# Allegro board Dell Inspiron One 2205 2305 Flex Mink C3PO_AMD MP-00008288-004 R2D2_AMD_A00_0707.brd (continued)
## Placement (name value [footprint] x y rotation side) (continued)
R666  75R  [R0402]  16.01 61.98 180 bottom
R667  0R  [R0402]  81.67 71.63 270 bottom
R668  0R  [R0402]  79.89 55.75 90 bottom
R669  2K2  [R0402]  109.1 58.67 0 bottom
R670  11K8  [R0402]  89.09 68.45 270 bottom
R671  931R  [R0402]  108.34 64.77 180 bottom
R672  2K2  [R0402]  109.1 57.4 0 bottom
R673  2K2  [R0402]  109.1 56.13 0 bottom
R674  20K  [R0402]  24.27 57.53 270 bottom
R675  2K2  [R0402]  109.1 54.86 0 bottom
R676  10K  [R0402]  109.1 59.94 180 bottom
R677  10K  [R0402]  81.29 49.4 90 bottom
R678  10K  [R0402]  79 49.4 90 bottom
R679  0R  [R0402]  73.9 57.38 0 bottom
R680  1K  [R0402]  17.28 50.42 0 bottom
R681  0R  [R0402]  73.9 56.24 0 bottom
R682  0R  [R0603]  106.18 52.7 180 bottom
R683  10K  [R0402]  97.67 58.67 270 bottom
R684  100K  [R0402]  178.7 45.34 90 bottom
R685  200K  [R0402]  175.91 48.01 180 bottom
R686  0R  [R0402]  13.09 54.48 180 bottom
R687  0R  [R0603]  93.36 50.67 180 bottom
R688  0R  [R0402]  97.67 53.85 0 bottom
R689  8K2  [R0402]  72.65 52.96 0 bottom
R690  10K  [R0402]  81.04 55.75 270 bottom
R691  4K7  [R0402]  17.28 51.56 180 bottom
R692  1K  [R0402]  164.98 54.74 270 bottom
R693  1K  [R0402]  46.11 41.15 90 bottom
R694  0R  [R0402]  88.91 51.31 0 bottom
R695  1K  [R0402]  18.04 44.2 0 bottom
R696  0R  [R0603]  95.64 52.7 270 bottom
R697  2K2  [R0402]  82.69 52.32 270 bottom
R698  2K2  [R0402]  80.15 52.32 270 bottom
R699  2K2  [R0402]  77.86 52.32 270 bottom
R700  0R  [R0402]  72.27 48.77 0 bottom
R701  10K  [R0402]  27.95 43.81 270 bottom
R702  20K  [R0402]  26.68 43.81 270 bottom
R703  10K  [R0402]  91.32 50.93 270 bottom
R704  0R  [R0402]  190.76 42.67 270 bottom
R705  0R  [R0402]  189.62 42.67 270 bottom
R706  0R  [R0402]  72.3 47.57 0 bottom
R707  0R  [R0402]  124.79 36.96 90 bottom
R708  0R  [R0402]  123.71 36.96 90 bottom
R709  0R  [R0402]  120.66 36.96 90 bottom
R710  15K  [R0402]  119.64 36.96 90 bottom
R711  1K  [R0402]  118.63 36.96 90 bottom
R712  1K  [R0402]  48.21 39.37 180 bottom
R713  4K7  [R0402]  18.04 45.34 180 bottom
R714  0R  [R0603]  87.39 48.13 270 bottom
R715  0R  [R0402]  45.86 35.37 0 bottom
R716  100K  [R0402]  184.29 42.8 180 bottom
R717  0R  [R0402]  43.32 36.45 0 bottom
R718  0R  [R0402]  43.32 37.66 0 bottom
R719  10K  [R0402]  122.69 36.96 270 bottom
R720  10K  [R0402]  121.68 36.96 270 bottom
R721  1K  [R0402]  129.17 34.54 180 bottom
R722  0R  [R0402]  43 33.27 180 bottom
R723  270R  [R0402]  132.85 34.04 180 bottom
R724  10K  [R0402]  120.41 40.89 180 bottom
R725  100K  [R0402]  187.08 39.62 180 bottom
R726  0R  [R0402]  48.91 32.64 0 bottom
R727  0R  [R0402]  45.73 31.37 0 bottom
R728  0R  [R0402]  43.44 31.37 0 bottom
R729  8K2  [R0402]  112.43 27.56 90 bottom
R730  10K  [R0402]  120.91 39.24 270 bottom
R731  1K  [R0402]  115.83 25.15 90 bottom
R732  0R  [R0805]  84.21 133.22 0 top
R733  0R  [R0805]  128.92 37.59 270 bottom
R734  10K  [R0402]  46.11 29.72 270 bottom
R735  0R  [R0402]  114.18 27.05 0 bottom
R736  1K  [R0402]  81.42 206.25 180 top
R737  10K  [R0402]  114.18 26.04 0 bottom
R738  0R  [R0402]  45.1 29.72 90 bottom
R739  1K  [R0402]  114.18 25.02 0 bottom
R740  0R  [R0603]  27.25 25.65 270 bottom
R741  10K  [R0402]  114.18 24 0 bottom
R742  15K  [R0402]  12.2 25.91 270 bottom
R743  100K  [R0603]  25.73 25.65 90 bottom
R744  10K  [R0402]  13.35 28.32 270 top
R745  10K  [R0402]  27.32 22.48 90 bottom
R746  0R  [R0402]  111.36 27.56 270 bottom
R747  2K49  [R0402]  128.47 25.65 270 bottom
R748  0R  [R0402]  44.46 17.53 270 bottom
R749  0R  [R0402]  43.44 17.53 270 bottom
R750  75R  [R0402]  104.23 15.21 0 bottom
R751  100K  [R0402]  26.93 16.7 270 bottom
R752  4K7  [R0402]  12.58 23.05 90 bottom
R753  0R  [R0402]  14.43 24.64 90 top
R754  47K  [R0402]  140.98 15.88 180 bottom
R755  47K  [R0402]  138.82 15.88 180 bottom
R756  0R  [R0603]  33.41 10.72 0 bottom
R757  7K68  [R0603]  24.08 23.11 90 bottom
R758  75R  [R0402]  104.79 12.89 90 bottom
R759  100R  [R0402]  15.38 7.87 0 bottom
R760  0R  [R0603]  30.24 12.57 90 bottom
R761  200K  [R0603]  155.14 20.7 270 bottom
R762  4K7  [R0402]  13.79 7.37 270 bottom
R763  10K  [R0402]  12.77 7.37 270 bottom
R764  0R  [R0402]  11.76 7.37 270 bottom
R765  0R  [R0402]  9.73 7.37 270 bottom
R766  0R  [R0402]  8.71 7.37 270 bottom
R767  2K2  [R0603]  7.44 7.11 90 bottom
R768  22R  [R0402]  6.17 7.18 270 bottom
R769  0R  [R0402]  10.74 7.37 90 bottom
R770  330R  [R0603]  7.95 3.87 90 bottom
R771  1K  [R0402]  27.7 207.26 90 top
R772  20K  [R0402]  99.58 121.16 0 bottom
R773  0R  [R0603]  33.41 8.89 0 bottom
R774  20K  [R0402]  21.66 26.42 90 top
R775  1K  [R0402]  74.31 202.44 270 top
R776  1K  [R0402]  82.81 201.17 90 top
R980  10K  [R0402]  8.46 22.54 180 bottom
R987  0R  [R0402]  10.81 22.54 180 bottom
R989  8K2  [R0402]  21.6 35.69 270 top
R1017  3K3  [R0402]  13.35 26.04 270 top
R2122  4K7  [R0402]  45.86 33.27 180 bottom
R2123  4K7  [R0402]  45.86 34.35 180 bottom
R2124  4K7  [R0402]  40.78 35.69 0 top
R2125  4K7  [R0402]  40.78 36.83 0 top
R2126  0R  [R1206]  77.67 172.91 270 top
R2127  0R  [R1206]  72.4 173.23 270 top
R2128  0R  [R1206]  85.67 133.73 180 bottom
R2129  0R  [R1206]  52.33 161.61 90 bottom
R2130  0R  [R1206]  41.35 143.7 270 bottom
S1  TACT  [DCON_SW_4_DIPTRONICS]  8.05 167.62 90 bottom
S2  TACT  [DCON_SW_4_DIPTRONICS]  8.05 153.62 90 bottom
S3  PUBTON  [DCON_PUBTON_8_HIGHLY-A]  10.79 12.92 270 bottom
SW1  TSXH-2GL  [SCON_SW_4_HUA-JIE]  111.14 34.92 90 top
TP1  STP  [TP30]  20.87 227.84 0 top
TP2  STP  [TP30]  22.84 227.84 0 top
TP3  STP  [TP30]  24.74 227.84 0 top
TP4  STP  [TP30]  26.65 227.84 0 top
TP5  STP  [TP30]  28.55 227.84 0 top
TP6  STP  [TP30]  20.87 225.81 0 top
TP7  STP  [TP30]  22.84 225.81 0 top
TP8  STP  [TP30]  24.74 225.81 0 top
TP9  STP  [TP30]  26.65 225.81 0 top
TP10  STP  [TP30]  28.55 225.81 0 top
TP11  STP  [TP30]  28.93 210.31 0 top
TP12  STP  [TP30]  30.84 210.31 0 top
TP13  STP  [TP30]  32.74 210.31 0 top
TP14  STP  [TP30]  34.65 210.31 0 top
TP15  STP  [TP30]  36.55 210.31 0 top
TP16  STP  [TP30]  17.03 208.53 0 top
TP17  STP  [TP30]  18.93 208.53 0 top
TP18  STP  [TP30]  20.84 208.53 0 top
TP19  STP  [TP30]  22.74 208.53 0 top
TP20  STP  [TP30]  24.65 208.53 0 top
TP21  STP  [TP30]  28.93 208.34 0 top
TP22  STP  [TP30]  30.84 208.34 0 top
TP23  STP  [TP30]  32.74 208.34 0 top
TP24  STP  [TP30]  34.65 208.34 0 top
TP25  STP  [TP30]  36.55 208.34 0 top
TP26  STP  [TP30]  46.79 208.03 0 top
TP27  STP  [TP30]  17.03 206.63 0 top
TP28  STP  [TP30]  18.93 206.63 0 top
TP29  STP  [TP30]  20.84 206.63 0 top
TP30  STP  [TP30]  22.74 206.63 0 top
TP31  STP  [TP30]  24.65 206.63 0 top
TP32  STP  [TP30]  46.87 205.99 0 top
TP33  STP  [TP30]  93.36 162.69 270 top
TP34  STP  [TP30]  89.29 161.54 270 top
TP35  STP  [TP30]  93.36 161.42 270 top
TP36  STP  [TP30]  91.32 164.34 0 top
TP37  STP  [TP30]  89.29 160.27 270 top
TP38  STP  [TP30]  91.2 159.89 270 top
TP39  STP  [TP30]  56.78 163.32 0 top
TP40  STP  [TP30]  91.32 163.07 0 top
TP41  STP  [TP30]  91.2 158.62 270 top
TP42  STP  [TP30]  93.36 158.37 270 top
TP43  STP  [TP30]  89.29 157.23 270 top
TP44  STP  [TP30]  44.84 161.04 0 top
TP45  STP  [TP30]  93.36 157.1 270 top
TP46  STP  [TP30]  89.29 155.96 270 top
TP47  STP  [TP30]  44.84 159.77 0 top
TP48  STP  [TP30]  91.2 155.57 270 top
TP49  STP  [TP30]  91.2 154.31 270 top
TP50  STP  [TP30]  93.23 154.05 270 top
TP51  STP  [TP30]  89.29 152.91 270 top
TP52  STP  [TP30]  89.29 151.64 270 top
TP53  STP  [TP30]  91.32 151.26 270 top
TP54  STP  [TP30]  91.32 149.99 270 top
TP55  STP  [TP30]  93.23 149.73 270 top
TP56  STP  [TP30]  93.23 152.78 0 top
TP57  STP  [TP30]  93.23 148.46 270 top
TP58  STP  [TP30]  160.03 146.94 180 top
TP59  STP  [TP30]  89.16 147.32 270 top
TP60  STP  [TP30]  155.78 149.96 0 top
TP61  STP  [TP30]  91.2 147.07 270 top
TP62  STP  [TP30]  155.79 148.38 0 top
TP63  STP  [TP30]  93.23 145.41 270 top
TP64  STP  [TP30]  89.16 148.59 0 top
TP65  STP  [TP30]  84.21 144.53 270 top
TP66  STP  [TP30]  158.64 146.89 0 top
TP67  STP  [TP30]  93.23 144.15 270 top
TP68  STP  [TP30]  84.21 143.26 270 top
TP69  STP  [TP30]  82.18 143 270 top
TP70  STP  [TP30]  91.2 145.8 0 top
TP71  STP  [TP30]  82.18 141.73 270 top
TP72  STP  [TP30]  84.21 141.35 270 top
TP73  STP  [TP30]  155.8 142.93 0 top
TP74  STP  [TP30]  84.21 140.08 270 top
TP75  STP  [TP30]  82.5 139.83 270 top
TP76  STP  [TP30]  82.5 138.56 270 top
TP77  STP  [TP30]  84.72 138.18 270 top
TP78  STP  [TP30]  84.72 136.91 270 top
TP79  STP  [TP30]  155.83 138.45 0 top
TP80  STP  [TP30]  155.85 135.4 0 top
TP81  STP  [TP30]  82.56 136.4 0 top
TP82  STP  [TP30]  82.56 135.13 0 top
TP83  STP  [TP30]  108.02 120.97 0 top
TP84  STP  [TP30]  129.4 120.45 0 top
TP85  STP  [TP30]  111.64 120.02 0 top
TP86  STP  [TP30]  130.47 119.28 0 top
TP87  STP  [TP30]  96.66 118.75 0 top
TP88  STP  [TP30]  111.64 118.11 0 top
TP89  STP  [TP30]  131.66 118.16 0 top
TP90  STP  [TP30]  97.86 117.2 0 top
TP91  STP  [TP30]  104.66 117.09 0 top
TP92  STP  [TP30]  95.9 116.71 0 top
TP93  STP  [TP30]  132.62 117.04 0 top
TP94  STP  [TP30]  109.1 115.82 0 top
TP95  STP  [TP30]  113.04 72.64 0 top
TP96  STP  [TP30]  77.61 55.24 0 top
TP97  STP  [TP30]  74.05 51.31 0 top
TP98  STP  [TP30]  85.1 49.59 0 top
TP99  STP  [TP30]  112.25 50.62 0 top
TP100  STP  [TP30]  86.75 49.02 0 top
TP101  STP  [TP30]  108.09 50.04 0 top
TP102  STP  [TP30]  91.58 42.67 0 top
TP103  STP  [TP30]  108.85 51.94 180 bottom
TP104  STP  [TP30]  87.01 221.23 180 bottom
TP105  STP  [TP30]  87.01 219.33 180 bottom
TP106  STP  [TP30]  86.94 217.42 180 bottom
TP107  STP  [TP30]  87.01 215.46 180 bottom
TP108  STP  [TP30]  114.44 174.62 180 bottom
TP109  STP  [TP30]  124.92 172.85 180 bottom
TP110  STP  [TP30]  114.06 172.47 180 bottom
TP111  STP  [TP30]  125.99 171.32 180 bottom
TP112  STP  [TP30]  107.58 171.83 180 bottom
TP113  STP  [TP30]  111.52 170.31 180 bottom
TP114  STP  [TP30]  127.01 170.05 180 bottom
TP115  STP  [TP30]  104.28 170.43 180 bottom
TP116  STP  [TP30]  126.25 168.59 180 bottom
TP117  STP  [TP30]  108.21 167.39 180 bottom
TP118  STP  [TP30]  114.56 167.26 180 bottom
TP119  STP  [TP30]  111.99 167.19 180 bottom
TP120  STP  [TP30]  103.01 168.28 180 bottom
TP121  STP  [TP30]  105.8 167.13 180 bottom
TP122  STP  [TP30]  100.85 166.37 180 bottom
TP123  STP  [TP30]  113.29 164.85 180 bottom
TP124  STP  [TP30]  109.48 164.85 180 bottom
TP125  STP  [TP30]  116.72 164.47 180 bottom
TP126  STP  [TP30]  102.88 165.61 180 bottom
TP127  STP  [TP30]  96.15 164.08 180 bottom
TP128  STP  [TP30]  109.48 163.58 180 bottom
TP129  STP  [TP30]  127.52 163.51 180 bottom
TP130  STP  [TP30]  126.19 163.51 180 bottom
TP131  STP  [TP30]  124.85 163.51 180 bottom
TP132  STP  [TP30]  123.45 163.51 180 bottom
TP133  STP  [TP30]  96.15 162.81 180 bottom
TP134  STP  [TP30]  98.05 162.43 180 bottom
TP135  STP  [TP30]  93.86 161.29 180 bottom
TP136  STP  [TP30]  98.05 161.16 180 bottom
TP137  STP  [TP30]  96.02 159.64 180 bottom
TP138  STP  [TP30]  93.86 160.02 180 bottom
TP139  STP  [TP30]  96.02 158.37 180 bottom
TP140  STP  [TP30]  98.05 158.12 180 bottom
TP141  STP  [TP30]  98.05 156.84 180 bottom
TP142  STP  [TP30]  93.99 156.84 180 bottom
TP143  STP  [TP30]  93.99 155.57 180 bottom
TP144  STP  [TP20]  65.42 155.3 180 bottom
TP145  STP  [TP30]  96.02 155.32 180 bottom
TP146  STP  [TP30]  96.02 154.05 180 bottom
TP147  STP  [TP20]  65.44 153.95 180 bottom
TP148  STP  [TP30]  98.05 153.67 180 bottom
TP149  STP  [TP20]  65.39 152.55 180 bottom
TP150  STP  [TP30]  98.05 152.4 180 bottom
TP151  STP  [TP30]  59.57 153.67 180 bottom
TP152  STP  [TP30]  93.99 152.53 180 bottom
TP153  STP  [TP30]  96.02 150.88 180 bottom
TP154  STP  [TP30]  136.35 150.81 180 bottom
TP155  STP  [TP30]  134.31 150.75 180 bottom
TP156  STP  [TP30]  93.99 151.26 180 bottom
TP157  STP  [TP30]  96.02 149.61 180 bottom
TP158  STP  [TP30]  98.05 149.22 180 bottom
TP159  STP  [TP30]  133.81 148.27 180 bottom
TP160  STP  [TP30]  132.47 148.27 180 bottom
TP161  STP  [TP30]  98.05 147.96 180 bottom
TP162  STP  [TP30]  93.99 147.96 180 bottom
TP163  STP  [TP30]  96.15 146.3 180 bottom
TP164  STP  [TP30]  133.68 145.73 180 bottom
TP165  STP  [TP30]  93.99 146.69 180 bottom
TP166  STP  [TP30]  96.15 145.03 180 bottom
TP167  STP  [TP30]  98.05 144.78 180 bottom
TP168  STP  [TP30]  98.05 143.51 180 bottom
TP169  STP  [TP30]  134.82 143.19 180 bottom
TP170  STP  [TP30]  93.99 143.64 180 bottom
TP171  STP  [TP30]  96.15 142.11 180 bottom
TP172  STP  [TP30]  93.99 142.37 180 bottom
TP173  STP  [TP30]  134.38 140.91 180 bottom
TP174  STP  [TP30]  96.15 140.84 180 bottom
TP175  STP  [TP30]  136.28 140.65 180 bottom
TP176  STP  [TP30]  138.72 140.53 180 bottom
TP177  STP  [TP30]  98.05 140.46 180 bottom
TP178  STP  [TP30]  111.01 139.7 180 bottom
TP179  STP  [TP30]  124.79 139.45 180 bottom
TP180  STP  [TP30]  127.33 139.38 180 bottom
TP181  STP  [TP30]  98.05 139.19 180 bottom
TP182  STP  [TP30]  126.06 138.11 180 bottom
TP183  STP  [TP30]  93.86 139.32 180 bottom
TP184  STP  [TP30]  96.02 137.67 180 bottom
TP185  STP  [TP30]  127.26 136.97 180 bottom
TP186  STP  [TP30]  93.86 138.05 180 bottom
TP187  STP  [TP30]  96.02 136.4 180 bottom
TP188  STP  [TP30]  98.05 136.14 180 bottom
TP189  STP  [TP30]  62.75 137.03 180 bottom
TP190  STP  [TP30]  64.69 137.02 180 bottom
TP191  STP  [TP30]  111.01 135.13 180 bottom
TP192  STP  [TP30]  98.05 134.77 180 bottom
TP193  STP  [TP30]  108.6 132.08 180 bottom
TP194  STP  [TP30]  108.47 130.18 180 bottom
TP195  STP  [TP30]  27.57 82.04 180 bottom
TP196  STP  [TP30]  81.16 80.54 180 bottom
TP197  STP  [TP30]  92.91 79.88 180 bottom
TP198  STP  [TP30]  85.91 78.95 180 bottom
TP199  STP  [TP30]  99.12 68.31 180 bottom
TP200  STP  [TP30]  89.67 59.82 180 bottom
TP201  STP  [TP30]  87.77 56.13 180 bottom
TP202  STP  [TP30]  47 52.35 0 top
TP203  STP  [TP30]  107.17 46.89 180 bottom
TP204  STP  [TP30]  50.43 40.2 180 bottom
TP205  STP  [TP30]  51.42 38.25 180 bottom
U1  RT9018B-25GQW  [QFN10_050P310W100HG]  138 236.04 0 top
U2  SN74LVC1G07  [SOT363_5P]  51.32 177.29 180 top
U3  RS880M  [BGA528_080P210L210W207H]  62.44 148.46 270 top
U4  RT9018B-25GQW  [QFN10_050P310W100HG]  23.51 144.02 90 top
U5  AU6437B52-GEF-GR  [QFN28_500L500W080HG]  21.78 130.85 270 top
U6  SKT941P  [BGA941_127P5115L4808W620H]  121 152.08 270 top
U7  RT9018B-25GQW  [QFN10_050P310W100HG]  110.2 105.26 180 top
U9  RT9018B-25GQW  [QFN10_050P310W100HG]  68.34 67.82 0 top
U10  SB820M  [BGA605_080P230L230W207H]  95.24 66.12 0 top
U11  NCT5572D  [LQFP64_700L700W160H]  47.51 37.47 180 top
U12  SST25VF032B-80-4I-S2A  [SO8_127P540W216H]  97.04 33.66 270 top
U13  NUP4201MR6T1G  [SOT23_6P]  120.41 21.72 0 top
U14  NUP4201MR6T1G  [SOT23_6P]  126.76 21.72 0 top
U15  SKT8P  [SKT_SSO8]  97.04 33.66 270 top
U16  ADM213EARSZ  [SSOP28_065P538W199H]  141.36 19.94 0 top
U17  NTMS4176P  [SO8_127P400W175H]  158.82 20.7 270 top
U18  AT24C02BN-SH  [SO8_127P400W175H]  80.27 231.01 0 bottom
U19  RT9018B-25GQW  [QFN10_050P310W100HG]  87.51 126.75 270 bottom
U20  ICS9LPRS482  [TSSOP56_050P620W120H]  32.84 100.98 180 bottom
U21  PRTR5V0U2X  [SOT143_4P]  61.42 67.5 180 bottom
U22  SN74AHC1G08  [SOT23_5P]  172.6 52.96 0 bottom
U23  ALC272-GR  [LQFP48_710L710W160H]  25.79 50.42 270 bottom
U24  RTL8111E-VB-GR  [QFN48_600L600W090HG]  122.8 30.36 180 bottom
U25  TDA1517ATW  [TSSOP20_065P450W110HG]  20.2 32.77 180 bottom
U26  SN74AHC1G32DBVR  [SOT23_5P]  11.12 19.94 180 bottom
Y1  25MHZ  [SCRY2_450W800L150H_TXC]  92.99 87.09 0 top
Y2  25MHZ  [DCRY2_49US034H]  117.23 63.88 180 top
Y3  32.768KHZ  [SCRY4_140W670L130H]  78.52 44.4 0 top
Y4  14.31818MHZ  [SCRY2_450W800L150H_TXC]  44.4 101.16 90 bottom
Y5  25MHZ  [SCRY2_450W800L150H]  131.56 28.58 270 bottom

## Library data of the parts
B1 = BATTERY_H
C1 C2 C4-C6 C20 C23 C31 C33 C50 C79 C95 C98 C111-C113 C141 C144 C152 C209 C213 C221 C223-C225 C238 C240 C246 C251 C256 C278 C294 C308 C315 C345 C355 C370 C382 C383 C394 C396 C401 C420 C422 C423 C435-C437 C454 C480 C502 C512 C528 C533 PC6 PC12 PC13 PC17 PC21 PC23 PC27 PC29 PC38 PC39 PC76 PC77 PC82 PC96 PC103 PC104 PC108 PC111 PC126-PC136 PC141 PC142 PC146 PC149 = C: signal model: DEFAULT_CAPACITOR_1e+07pF_2_1
C3 C21 C353 C490 C491 C507 C520 PC5 = C: signal model: DEFAULT_CAPACITOR_100pF_2_1
C7 C22 C52 C63 C70 C83 C91-C93 C102 C110 C120 C128 C145 C162 C200-C202 C206 C216 C219 C226 C245 C263 C266 C268 C274 C304 C346 C350 C373 C375 C381 C390 C402 C430 C451 C466 C467 C476 C479 C483 C484 C486 C492 C550 C553 PC24 PC30 PC31 PC33-PC37 PC99 PC100 PC120 = C: signal model: DEFAULT_CAPACITOR_1e+06pF_2_1
C8-C19 C25-C29 C32 C34 C36-C49 C51 C53 C55-C58 C61 C64 C68 C69 C73 C82 C87 C89 C94 C104-C109 C114 C116 C119 C122-C124 C126 C127 C129-C140 C142 C148 C150 C153 C157-C159 C163 C164 C167 C169-C180 C182 C183 C185 C186 C189-C197 C207 C211 C212 C217 C218 C227 C232 C233 C241-C243 C248 C253 C254 C257 C260 C264 C265 C269 C272 C275 C277 C284 C286 C287 C290 C295-C300 C302 C303 C305 C309-C311 C318 C320 C323-C325 C327 C330 C331 C342-C344 C347 C349 C352 C364 C367 C368 C379 C386 C387 C389 C391 C393 C395 C397 C399 C400 C403-C406 C408-C410 C412-C414 C416 C417 C419 C438 C439 C441 C444 C447 C448 C450 C453 C456 C457 C459 C462-C464 C469 C471-C475 C477 C478 C481 C487-C489 C493 C495 C496 C503-C505 C508 C509 C511 C515 C517 C521 C522 C525-C527 C537 C539-C543 C545 C548 C549 C551 PC7 PC9 PC16 PC19 PC20 PC25 PC40 PC41 PC43 PC52 PC55 PC57 PC60 PC63 PC68-PC70 PC75 PC79 PC83 PC90 PC93 PC95 PC98 PC102 PC105 PC116 PC138 PC139 PC147 PC148 PC152 = C: signal model: DEFAULT_CAPACITOR_100000pF_2_1
C24 C35 C62 C66 C67 C71 C88 C181 C348 C354 C440 C449 C499 C506 C536 C544 PC3 = C: signal model: DEFAULT_CAPACITOR_10pF_2_1
C30 C54 C117 C125 C234 C236 C351 PC89 PC106 PC137 PC143 = C: signal model: DEFAULT_CAPACITOR_1000pF_2_1
C59 C74 C81 C214 C215 C228-C231 C235 C237 C271 C317 C322 C365 C366 C424 C427 C445 C510 C532 PC81 PC145 = C: signal model: DEFAULT_CAPACITOR_10000pF_2_1
C60 C84 C151 C155 C166 C199 C208 C220 C239 C258 C262 C312 C388 C392 C398 C411 C485 C497 C501 C538 C546 PC28 PC42 PC59 PC62 PC65 PC66 PC71 PC72 PC88 PC97 PC110 PC112 PC117 PC118 PC121 PC123-PC125 PC151 = C: signal model: DEFAULT_CAPACITOR_2.2e+07pF_2_1
C72 C75 C77 C78 C80 C316 C358 C361 C363 C380 C418 C431 C432 C518 PC14 PC15 PC26 PC114 PC115 = C: signal model: DEFAULT_CAPACITOR_220000pF_2_1
C76 C285 C288 C291 C293 PC8 PC10 PC80 = C: signal model: DEFAULT_CAPACITOR_2200pF_2_1
C85 C86 = C: signal model: DEFAULT_CAPACITOR_3900pF_2_1
C90 C99 C101 C115 C118 C121 C143 C146 C147 C149 C154 C156 C160 C161 C281 C282 C374 C384 C407 C421 C428 C434 C465 PC1 PC91 PC150 = C: signal model: DEFAULT_CAPACITOR_4.7e+06pF_2_1
C96 C97 C359 C377 C385 C425 C426 C429 C433 = C: signal model: DEFAULT_CAPACITOR_180pF_2_1
C100 C103 C165 C168 C203 C244 C249 C270 C283 C356 C360 C372 C376 C378 C415 C455 C458 C460 C461 C468 C470 C482 C494 C498 C500 C516 = C: signal model: DEFAULT_CAPACITOR_2.2e+06pF_2_1
C184 C188 C252 C362 C523 C524 C531 C534 C547 C554-C557 C1457-C1460 C1462-C1465 PC153-PC160 PR87 = C
C187 C205 C210 C222 C247 C255 C267 C279 PC2 PC11 = C: signal model: DEFAULT_CAPACITOR_22pF_2_1
C198 C204 = C: signal model: DEFAULT_CAPACITOR_15pF_2_1
C250 = C: signal model: C_NOMODEL
C259 C273 = C: signal model: DEFAULT_CAPACITOR_18pF_2_1
C261 C280 = C: signal model: DEFAULT_CAPACITOR_150pF_2_1
C276 C313 C321 C369 C371 C552 = C: signal model: DEFAULT_CAPACITOR_470pF_2_1
C289 C292 C306 = C: room: 33vaux; signal model: DEFAULT_CAPACITOR_100000pF_2_1
C301 = EC: signal model: DEFAULT_CAPACITOR_100000pF_2_1
C307 C314 PC107 PC119 = C: signal model: DEFAULT_CAPACITOR_4700pF_2_1
C319 C326 C328 C329 C332 C333 C446 C452 = EC: signal model: DEFAULT_CAPACITOR_1e+08pF_2_1
C334-C341 = C: signal model: DEFAULT_CAPACITOR_220pF_2_1
C357 = C: signal model: DEFAULT_CAPACITOR_3300pF_2_1
C442 C443 C529 C530 PC64 PC67 = C: signal model: DEFAULT_CAPACITOR_33pF_2_1
C513 = C: signal model: DEFAULT_CAPACITOR_47000pF_2_1
C514 EC11 = EC
C519 C535 = C: signal model: DEFAULT_CAPACITOR_470000pF_2_1
CN1 = SLOT_MXM3_0
CN2 CN5 = SLOT_PCIE-52P
CN6 CN8 = CONN_WFR_30P
CN7 CN9 = CONN_0040P_00+4P
CN10 = CONN_WFR_4P_6
CN11 CN12 = CONN_SATA_7P
CN13 = SOCKET_42P_1
CN14-CN19 = CONN_USBX1_4P
CN20 CN21 = JACK6P
CN22 = JACK5P+3P_1
CN23 = CONN_RJ45_14P_A
CN24 = DCJACK_2P+6P
CN25 = CONN_WFR_8P_1
CN26 = CONN_WFR_6P
CN27 = CONN_WFR_14P
CN28 = HDR_NOBOX_1X6_K6
CN29 = HDR_NOBOX_1X3_K3
CN30 = HDR_NOBOX_1X6
CN31 = CONN_WFR_8P_2
CN32 = CONN_WFR_4P
CN33-CN35 = CONN_WFR_4P_1
D1-D7 D9 PD1 = DIODE
D8 D10-D12 = DIODE_SOKY_3P_BAT54C
D13 D17 D18 = DIODE_SCH_2P_SMAJ12A_13_F
D14-D16 = DIO_ESD_3P_1
EC1 EC2 PC92 = EC: signal model: DEFAULT_CAPACITOR_2.2e+08pF_2_1
F2-F4 = FUSE
H1-H6 = FMARK
J1 J2 = SLOT_DDR3_240P
J3 = HDR_NO BOX_2X13_K25
J4 = HDR_NO BOX_2X3
J6 = HDR_NOBOX_2X5_K10
L1 L14 = L_FB: signal model: DEFAULT_INDUCTOR_1e+011nH_2_1
L2 L20-L22 L26 L27 L29 L30 = L_FB: signal model: DEFAULT_INDUCTOR_3e+010nH_2_1
L3 = L_FB: signal model: DEFAULT_INDUCTOR_8e+010nH_2_1
L4 = L: signal model: DEFAULT_INDUCTOR_150nH_2_1
L5 L6 L10 = L: signal model: DEFAULT_INDUCTOR_360nH_2_1
L8 L9 L11 L13 L15 L23 L24 L40 L42-L46 L53 L55-L59 L61-L65 L74 L80 = L: signal model: DEFAULT_INDUCTOR_2.2e+011nH_2_1
L16-L19 L50 L69-L73 L75-L79 = L_FB: signal model: DEFAULT_INDUCTOR_6e+011nH_2_1
L25 L31 L32 L35 L60 = L: signal model: DEFAULT_INDUCTOR_7e+010nH_2_1
L28 L34 L41 = L: signal model: DEFAULT_INDUCTOR_1.2e+011nH_2_1
L33 = L_FB: signal model: DEFAULT_INDUCTOR_6e+010nH_2_1
L36-L39 L51 L52 = L_4P_SMT: signal model: L
L47 = L
L66 = L: signal model: DEFAULT_INDUCTOR_2200nH_2_1
L67 L68 = L_FB: signal model: DEFAULT_INDUCTOR_1.2e+011nH_2_1
L82 = L_FB
LED1 LED2 = LED
LED3 = LED_1
M1-M8 = STEEL_INSERT
MH1-MH10 = M_HOLE_A
PC4 PC58 PC86 PC94 PC101 PC109 PC113 PC140 = C: signal model: DEFAULT_CAPACITOR_1500pF_2_1
PC18 = C: signal model: DEFAULT_CAPACITOR_33000pF_2_1
PC22 PC32 PC44 PC45 PC47-PC51 PC53 PC54 PC56 PC61 = EC: signal model: DEFAULT_CAPACITOR_5.6e+08pF_2_1
PC46 = C: signal model: DEFAULT_CAPACITOR_5.6e+08pF_2_1
PC73 PC74 PC78 PC84 PC85 PC87 PC144 = EC: signal model: DEFAULT_CAPACITOR_3.3e+08pF_2_1
PC122 = C: signal model: DEFAULT_CAPACITOR_2000pF_2_1
PL1 PL5-PL7 PL10 PL12 PL14 PL15 = L_FB: signal model: DEFAULT_RESISTOR_80OHM_2_1
PL2 = L: signal model: DEFAULT_INDUCTOR_1000nH_2_1
PL3 = L: signal model: DEFAULT_INDUCTOR_680nH_2_1
PL4 PL11 = L: signal model: DEFAULT_INDUCTOR_1500nH_2_1
PL8 = L_FB: signal model: DEFAULT_RESISTOR_60OHM_2_1
PL9 = L: signal model: DEFAULT_INDUCTOR_10000nH_2_1
PL13 = L: signal model: DEFAULT_INDUCTOR_3300nH_2_1
PQ1-PQ8 PQ10 PQ12-PQ15 = MOSFET_N_8P_BSC057N03LS
PQ9 PQ11 = MOSFET_D_8P_FDMS9600S
PR1 PR5 PR34 PR76 PR77 = R: signal model: DEFAULT_RESISTOR_4.7OHM_2_1
PR2 R230 = R: signal model: DEFAULT_RESISTOR_10200OHM_2_1
PR3 PR4 PR10 PR11 PR13 PR14 PR17 PR22 PR24 PR26 PR36 PR44 PR45 PR53 PR55 PR56 PR59 PR65 PR69 PR75 PR83 PR84 R5 R17 R26 R28 R29 R31-R33 R39 R40 R45-R48 R51 R58 R62 R73 R75-R87 R89 R91 R95 R98 R101 R102 R104-R106 R108 R112 R113 R115 R120 R123 R124 R126 R131 R134 R136 R139 R141 R143 R152 R154 R156 R158 R160 R161 R164 R166 R168 R169 R171-R176 R181 R186 R189-R192 R196 R197 R200 R202-R205 R207 R210 R211 R222 R225 R227 R233-R236 R239 R247 R250 R256 R257 R261 R263 R269 R276 R277 R281 R291 R298 R299 R301 R303 R308 R309 R312 R320 R324 R330-R332 R343 R344 R346 R347 R353 R356 R358 R362 R364-R368 R377 R380-R383 R385 R388 R392 R394 R401 R409 R410 R413 R414 R432 R434 R435 R447-R449 R453 R454 R456-R458 R466 R469 R471-R474 R477 R478 R480 R485 R486 R489 R496 R500-R508 R513-R516 R526 R528-R531 R535 R536 R538 R539 R542 R549 R551-R554 R556-R558 R561 R564-R566 R568-R570 R583 R585-R588 R590 R591 R603 R604 R607 R608 R617-R626 R629 R633 R638-R641 R647 R648 R650-R653 R657 R658 R660 R662 R665 R667 R668 R679 R681 R682 R686-R688 R694 R696 R700 R704-R707 R714 R715 R717 R726-R728 R733 R740 R743 R748-R750 R753 R756-R758 R760 R765 R766 R769 = R: signal model: DEFAULT_RESISTOR_0.001OHM_2_1
PR6 PR8 PR20 R1 R3 R6 R59 R60 R121 R122 R137 R140 R177 R195 R198 R226 R244 R272 R280 R282 R297 R300 R302 R355 R359 R360 R363 R370-R373 R391 R393 R412 R416 R431 R438 R442 R446 R459-R464 R483 R499 R509 R540 R543-R545 R548 R555 R718 R722 R723 R744 R752 R762 = R: signal model: DEFAULT_RESISTOR_4700OHM_2_1
PR7 PR25 PR28 PR30 PR38 PR54 PR68 PR73 PR74 PR78 PR80 PR81 R52-R54 R532 R533 = R: signal model: DEFAULT_RESISTOR_2.2OHM_2_1
PR9 PR32 PR70 PR71 R34 R35 R41 R50 R74 R99 R100 R107 R213 R286 R307 R317 R323 R337 R348 R357 R487 R491 R494 R497 R632 R644 R659 R684 R739 R741 R751 = R: signal model: DEFAULT_RESISTOR_100000OHM_2_1
PR12 PR63 R2 R4 R8 R11 R16 R21 R56 R57 R66 R67 R117 R132 R145 R148 R180 R183 R193 R217 R219 R224 R237 R249 R260 R278 R289 R316 R419 R433 R437 R465 R475 R479 R481 R482 R484 R498 R522 R523 R567 R580 R595 R597 R611 R664 R680 R692 R693 R695 R711 R712 R731 = R: signal model: DEFAULT_RESISTOR_1000OHM_2_1
PR15 PR23 PR33 PR67 R38 R44 R55 R61 R63 R68 R96 R146 R157 R167 R179 R274 R571 R602 R708 R759 = R: signal model: DEFAULT_RESISTOR_100OHM_2_1
PR16 R151 R159 R163 R194 R251 R259 R264 R273 R350 R351 R375 R402 R642 R646 R669 R672 R673 R675 R691 R697-R699 R713 = R: signal model: DEFAULT_RESISTOR_2200OHM_2_1
PR18 PR66 R90 R92 R94 R661 R666 = R: signal model: DEFAULT_RESISTOR_75OHM_2_1
PR19 R149 R296 R573 = R: signal model: DEFAULT_RESISTOR_10OHM_2_1
PR21 = R: signal model: DEFAULT_RESISTOR_619000OHM_2_1
PR27 PR40 PR50 PR60 PR72 PR79 PR85 R7 R10 R12 R14 R24 R43 R125 R147 R182 R218 R221 R231 R232 R238 R262 R265 R270 R271 R275 R279 R285 R287 R290 R292-R295 R304 R305 R310 R313 R315 R318 R321 R325 R326 R335 R340-R342 R361 R369 R378 R384 R389 R390 R403-R408 R415 R420 R423 R425-R428 R436 R441 R443-R445 R450 R451 R467 R468 R559 R562 R578 R592-R594 R598 R610 R612 R613 R627 R628 R630 R631 R634 R635 R643 R649 R654 R655 R676-R678 R683 R690 R701 R703 R716 R719 R720 R724 R725 R730 R734 R737 R763 R770 = R: signal model: DEFAULT_RESISTOR_10000OHM_2_1
PR29 = C: signal model: DEFAULT_RESISTOR_10000OHM_2_1
PR31 PR35 = R: signal model: DEFAULT_RESISTOR_2400OHM_2_1
PR37 = R: signal model: DEFAULT_RESISTOR_12400OHM_2_1
PR39 PR46 PR51 PR57 R319 R429 R452 R455 R685 = R: signal model: DEFAULT_RESISTOR_200000OHM_2_1
PR41 = R: signal model: DEFAULT_RESISTOR_7680OHM_2_1
PR42 = R: signal model: DEFAULT_RESISTOR_10500OHM_2_1
PR43 PR82 = R: signal model: DEFAULT_RESISTOR_13300OHM_2_1
PR47 = R: signal model: DEFAULT_RESISTOR_73200OHM_2_1
PR48 = R: signal model: DEFAULT_RESISTOR_105000OHM_2_1
PR49 = R: signal model: DEFAULT_RESISTOR_121000OHM_2_1
PR52 = R: signal model: DEFAULT_RESISTOR_71500OHM_2_1
PR58 = R: signal model: DEFAULT_RESISTOR_133000OHM_2_1
PR61 = R: signal model: DEFAULT_RESISTOR_82000OHM_2_1
PR62 = R: signal model: DEFAULT_RESISTOR_390000OHM_2_1
PR64 = R: signal model: DEFAULT_RESISTOR_14000OHM_2_1
PR86 R209 R241-R243 R245 R246 R248 R253 R258 R411 R418 R424 R732 R736 R771-R776 R980 R987 R989 R1017 R2122-R2130 = R
PU1 PU4 PU5 = IC_PWM_8P_NCP5359A
PU2 = IC_PWM_48P_NCP5393A
PU3 = IC_PWM_24P_RT8207A
PU6 PU7 = IC_PWM_10P_TPS51218
PU8 = IC_PWM_8P_RT8272
PU9 = IC_PWM_32P_RT8206A-B
Q1 Q2 Q6 Q18 Q19 Q22 Q40 Q42-Q44 Q51 Q64-Q66 Q96 = MOSFET_N_2
Q3 Q12 Q13 Q15 Q20 Q21 Q23-Q25 Q28 Q36-Q38 Q41 Q46 Q48 Q54 Q55 Q57 Q61 Q62 Q70 = MOSFET_N_4
Q4 Q5 = MOSFET-N_2
Q7 Q17 Q608 = MOSFET_N_3P_FDV301N
Q8 Q9 Q27 Q29 Q33 Q35 Q45 Q60 = BJT_NPN
Q10 Q11 Q14 Q16 Q32 Q39 Q53 = BJT_NPN_2
Q26 Q30 Q31 Q47 = MOSFET_N_8P_RSS090N03TB
Q34 = DIO_SCH_3P_BAT54ALT1G
Q49 Q50 Q58 U13 U14 = DIODE_NOR_6P_SRV05-4
Q56 Q63 Q67 = MOSFET_P
Q59 = MOSFET_N_8P
Q609 = MOSFET_D_6P_2
R9 R13 R15 R65 R70-R72 R93 R97 R144 = R: signal model: DEFAULT_RESISTOR_150OHM_2_1
R18 = R: signal model: DEFAULT_RESISTOR_27OHM_2_1
R19 R23 = R: signal model: DEFAULT_RESISTOR_6800OHM_2_1
R20 R208 R214 R223 R240 R541 = R: signal model: DEFAULT_RESISTOR_300OHM_2_1
R22 R42 R49 R69 R228 R284 R314 R322 R354 R422 R470 R524 R525 R527 R581 R582 R589 R599 R605 R606 R656 R689 R729 = R: signal model: DEFAULT_RESISTOR_8200OHM_2_1
R25 R742 = R: signal model: DEFAULT_RESISTOR_560OHM_2_1
R27 = R: signal model: DEFAULT_RESISTOR_4420OHM_2_1
R30 R36 R37 = R: signal model: DEFAULT_RESISTOR_4220OHM_2_1
R64 R379 R396-R400 R417 R560 R563 R636 R637 R768 = R: signal model: DEFAULT_RESISTOR_22OHM_2_1
R88 R283 = R: signal model: DEFAULT_RESISTOR_21500OHM_2_1
R103 R537 = R: signal model: DEFAULT_RESISTOR_21OHM_2_1
R109 R170 R333 R336 R488 R764 R767 = R: signal model: DEFAULT_RESISTOR_330OHM_2_1
R110 R111 = R: signal model: DEFAULT_RESISTOR_511OHM_2_1
R114 = R: signal model: DEFAULT_RESISTOR_169OHM_2_1
R116 R127-R130 R547 = R: signal model: DEFAULT_RESISTOR_3000OHM_2_1
R118 R119 R252 R439 R674 = R: signal model: DEFAULT_RESISTOR_20000OHM_2_1
R133 R345 = R: signal model: DEFAULT_RESISTOR_1500OHM_2_1
R135 = R: signal model: DEFAULT_RESISTOR_1800OHM_2_1
R138 R142 R201 R215 R574-R577 = R: signal model: DEFAULT_RESISTOR_301OHM_2_1
R150 = R: signal model: DEFAULT_RESISTOR_8660OHM_2_1
R153 R155 = R: signal model: DEFAULT_RESISTOR_49.9OHM_2_1
R162 R178 = R: signal model: DEFAULT_RESISTOR_40.2OHM_2_1
R165 = R: signal model: DEFAULT_RESISTOR_120OHM_2_1
R184 R185 = R: signal model: DEFAULT_RESISTOR_39.2OHM_2_1
R187 R255 = R: signal model: DEFAULT_RESISTOR_2000OHM_2_1
R188 R550 = R: signal model: DEFAULT_RESISTOR_1270OHM_2_1
R199 R511 R517 R663 = R: signal model: DEFAULT_RESISTOR_51000OHM_2_1
R206 R572 = R: signal model: DEFAULT_RESISTOR_44.2OHM_2_1
R216 = R: signal model: DEFAULT_RESISTOR_330000OHM_2_1
R220 R229 = R: signal model: DEFAULT_RESISTOR_20500OHM_2_1
R254 = R: signal model: DEFAULT_RESISTOR_590OHM_2_1
R288 = R: signal model: DEFAULT_RESISTOR_0.01OHM_2_1
R306 R387 R430 = R: signal model: DEFAULT_RESISTOR_49900OHM_2_1
R311 = R: signal model: DEFAULT_RESISTOR_4990OHM_2_1
R327-R329 R338 R339 R395 R421 R584 R600 R614-R616 = R: signal model: DEFAULT_RESISTOR_33OHM_2_1
R334 R490 R510 R520 R521 R745 = R: signal model: DEFAULT_RESISTOR_220OHM_2_1
R349 = R: signal model: DEFAULT_RESISTOR_0.02OHM_2_1
R352 R702 = R: signal model: DEFAULT_RESISTOR_39200OHM_2_1
R374 = R: signal model: DEFAULT_RESISTOR_30100OHM_2_1
R376 = R: signal model: DEFAULT_RESISTOR_3010OHM_2_1
R386 = R: signal model: DEFAULT_RESISTOR_510OHM_2_1
R440 = R: signal model: DEFAULT_RESISTOR_15OHM_2_1
R476 R492 R493 R495 R518 R754 R755 R761 = R: signal model: DEFAULT_RESISTOR_47000OHM_2_1
R512 R519 R645 = R: signal model: DEFAULT_RESISTOR_27000OHM_2_1
R534 = R: signal model: DEFAULT_RESISTOR_80.6OHM_2_1
R546 = R: signal model: DEFAULT_RESISTOR_715OHM_2_1
R579 = R: signal model: DEFAULT_RESISTOR_5100OHM_2_1
R596 = R: signal model: DEFAULT_RESISTOR_261OHM_2_1
R601 = R: signal model: DEFAULT_RESISTOR_158OHM_2_1
R609 = R: signal model: DEFAULT_RESISTOR_90.9OHM_2_1
R670 = R: signal model: DEFAULT_RESISTOR_11800OHM_2_1
R671 = R: signal model: DEFAULT_RESISTOR_931OHM_2_1
R709 R738 = R: signal model: DEFAULT_RESISTOR_1820OHM_2_1
R710 = R: signal model: DEFAULT_RESISTOR_15000OHM_2_1
R721 = R: signal model: DEFAULT_RESISTOR_22000OHM_2_1
R735 = R: signal model: DEFAULT_RESISTOR_1OHM_2_1
R746 = R: signal model: DEFAULT_RESISTOR_6200OHM_2_1
R747 = R: signal model: DEFAULT_RESISTOR_2490OHM_2_1
S1 S2 = SWITCH_4P_1
S3 = SWITCH_6P_LED_4
SW1 = SWITCH_4P
TP1-TP205 = TestPoint
U1 U4 U7 U9 U19 = IC_REG_10P_RT9018A
U2 = IC_LOGIC_5P_74LVC1G07GV: signal model: U69
U3 = IC_IGP_528P_RS880M
U5 = IC_USB_28P_AU6437B52-GEF-GR
U6 = SOCKET_941P
U10 = IC_ICH_605P_SB820M
U11 = IC_I/O_64P_NCT5572D
U12 = IC_FLASH_8P_SST25VF032B
U15 = SOCKET_8P
U16 = IC_UART_28P_ADM213EARSZ
U17 = MOSFET-P_8P_IRF7425PbF
U18 = IC_EEPROM_8P_AT24C02
U20 = IC_CLOCK_56P_ICS9LPRS482
U21 = DIODE_ESD_4P
U22 = IC_LOGIC_5P_SN74AHC1G08DBVR_1
U23 = IC_AUDIO_48P_ALC272
U24 = IC_LAN_48P_RTL8111E-VB-GR
U25 = IC_OP_20P_TDA1517ATW
U26 = IC_LOGIC_5P_SN74AHC1G32DBVR
Y1 Y2 Y4 Y5 = XTAL
Y3 = XTAL_FORK_1

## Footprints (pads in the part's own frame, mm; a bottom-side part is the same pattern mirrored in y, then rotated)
BGA528_080P210L210W207H
  round 0.305 smd: A2(-9.601,-8.801) A3(-9.601,-8.001) A4(-9.601,-7.201) A5(-9.2,-6.401) A6(-9.601,-5.601) A7(-9.2,-4.801) A8(-9.601,-4) A9(-9.2,-3.2) A10(-9.601,-2.4) A11(-9.2,-1.6) A12(-9.601,-0.8) A13(-9.2,0) A14(-9.601,0.8) A15(-9.2,1.6) A16(-9.601,2.4) A17(-9.2,3.2) A18(-9.601,4) A19(-9.2,4.801) A20(-9.601,5.601) A21(-9.2,6.401) A22(-9.601,7.201) A23(-9.601,8.001) A24(-9.601,8.801) A25(-9.601,9.601) AA1(6.401,-9.2) AA2(6.401,-8.4) AA4(6.401,-7.201) AA5(6.401,-6.401) AA6(6.401,-5.601) AA7(6.401,-4.801) AA8(6.401,-4) AA9(6.401,-2.751) AA11(6.401,-1.75) AA12(6.401,-0.749) AA14(6.401,0.749) AA15(6.401,1.75) AA17(6.401,2.751) AA18(6.401,4) AA19(6.401,4.801) AA20(6.401,5.601) AA21(6.401,6.401) AA22(6.401,7.201) AA24(6.401,8.4) AA25(6.401,9.2) AB1(7.201,-9.601) AB2(7.201,-8.801) AB3(7.201,-8.001) AB4(7.201,-7.201) AB5(7.201,-6.401) AB6(7.201,-5.601) AB7(7.201,-4.801) AB8(7.201,-4) AB9(7.201,-3.2) AB10(7.201,-2.4) AB11(7.201,-1.6) AB12(7.201,-0.8) AB13(7.201,0) AB14(7.201,0.8) AB15(7.201,1.6) AB16(7.201,2.4) AB17(7.201,3.2) AB18(7.201,4) AB19(7.201,4.801) AB20(7.201,5.601) AB21(7.201,6.401) AB22(7.201,7.201) AB23(7.201,8.001) AB24(7.201,8.801) AB25(7.201,9.601) AC1(8.001,-9.601) AC2(8.001,-8.801) AC3(8.001,-8.001) AC4(8.001,-7.201) AC6(8.001,-5.601) AC8(8.001,-4) AC10(8.001,-2.4) AC12(8.001,-0.8) AC14(8.001,0.8) AC16(8.001,2.4) AC18(8.001,4) AC20(8.001,5.601) AC22(8.001,7.201) AC23(8.001,8.001) AC24(8.001,8.801) AC25(8.001,9.601) AD1(8.801,-9.601) AD2(8.801,-8.801) AD3(8.801,-8.001) AD4(8.801,-7.201) AD5(8.4,-6.401) AD6(8.801,-5.601) AD7(8.4,-4.801) AD8(8.801,-4) AD9(8.4,-3.2) AD10(8.801,-2.4) AD11(8.4,-1.6) AD12(8.801,-0.8) AD13(8.4,0) AD14(8.801,0.8) AD15(8.4,1.6) AD16(8.801,2.4) AD17(8.4,3.2) AD18(8.801,4) AD19(8.4,4.801) AD20(8.801,5.601) AD21(8.4,6.401) AD22(8.801,7.201) AD23(8.801,8.001) AD24(8.801,8.801) AD25(8.801,9.601) AE1(9.601,-9.601) AE2(9.601,-8.801) AE3(9.601,-8.001) AE4(9.601,-7.201) AE5(9.2,-6.401) AE6(9.601,-5.601) AE7(9.2,-4.801) AE8(9.601,-4) AE9(9.2,-3.2) AE10(9.601,-2.4) AE11(9.2,-1.6) AE12(9.601,-0.8) AE13(9.2,0) AE14(9.601,0.8) AE15(9.2,1.6) AE16(9.601,2.4) AE17(9.2,3.2) AE18(9.601,4) AE19(9.2,4.801) AE20(9.601,5.601) AE21(9.2,6.401) AE22(9.601,7.201) AE23(9.601,8.001) AE24(9.601,8.801) AE25(9.601,9.601) B1(-8.801,-9.601) B2(-8.801,-8.801) B3(-8.801,-8.001) B4(-8.801,-7.201) B5(-8.4,-6.401) B6(-8.801,-5.601) B7(-8.4,-4.801) B8(-8.801,-4) B9(-8.4,-3.2) B10(-8.801,-2.4) B11(-8.4,-1.6) B12(-8.801,-0.8) B13(-8.4,0) B14(-8.801,0.8) B15(-8.4,1.6) B16(-8.801,2.4) B17(-8.4,3.2) B18(-8.801,4) B19(-8.4,4.801) B20(-8.801,5.601) B21(-8.4,6.401) B22(-8.801,7.201) B23(-8.801,8.001) B24(-8.801,8.801) B25(-8.801,9.601) C1(-8.001,-9.601) C2(-8.001,-8.801) C3(-8.001,-8.001) C4(-8.001,-7.201) C6(-8.001,-5.601) C8(-8.001,-4) C10(-8.001,-2.4) C12(-8.001,-0.8) C14(-8.001,0.8) C16(-8.001,2.4) C18(-8.001,4) C20(-8.001,5.601) C22(-8.001,7.201) C23(-8.001,8.001) C24(-8.001,8.801) C25(-8.001,9.601) D1(-7.201,-9.601) D2(-7.201,-8.801) D3(-7.201,-8.001) D4(-7.201,-7.201) D5(-7.201,-6.401) D6(-7.201,-5.601) D7(-7.201,-4.801) D8(-7.201,-4) D9(-7.201,-3.2) D10(-7.201,-2.4) D11(-7.201,-1.6) D12(-7.201,-0.8) D13(-7.201,0) D14(-7.201,0.8) D15(-7.201,1.6) D16(-7.201,2.4) D17(-7.201,3.2) D18(-7.201,4) D19(-7.201,4.801) D20(-7.201,5.601) D21(-7.201,6.401) D22(-7.201,7.201) D23(-7.201,8.001) D24(-7.201,8.801) D25(-7.201,9.601) E1(-6.401,-9.2) E2(-6.401,-8.4) E4(-6.401,-7.201) E5(-6.401,-6.401) E6(-6.401,-5.601) E7(-6.401,-4.801) E8(-6.401,-4) E9(-6.401,-2.751) E11(-6.401,-1.75) E12(-6.401,-0.749) E14(-6.401,0.749) E15(-6.401,1.75) E17(-6.401,2.751) E18(-6.401,4) E19(-6.401,4.801) E20(-6.401,5.601) E21(-6.401,6.401) E22(-6.401,7.201) E24(-6.401,8.4) E25(-6.401,9.2) F1(-5.601,-9.601) F2(-5.601,-8.801) F3(-5.601,-8.001) F4(-5.601,-7.201) F5(-5.601,-6.401) F6(-5.601,-5.601) F7(-5.601,-4.801) F8(-5.601,-4) F9(-5.601,-2.751) F11(-5.601,-1.75) F12(-5.601,-0.749) F14(-5.601,0.749) F15(-5.601,1.75) F17(-5.601,2.751) F18(-5.601,4) F19(-5.601,4.801) F20(-5.601,5.601) F21(-5.601,6.401) F22(-5.601,7.201) F23(-5.601,8.001) F24(-5.601,8.801) F25(-5.601,9.601) G1(-4.801,-9.2) G2(-4.801,-8.4) G4(-4.801,-7.201) G5(-4.801,-6.401) G6(-4.801,-5.601) G7(-4.801,-4.801) G8(-4.801,-4) G9(-4.801,-2.751) G11(-4.801,-1.75) G12(-4.801,-0.749) G14(-4.801,0.749) G15(-4.801,1.75) G17(-4.801,2.751) G18(-4.801,4) G19(-4.801,4.801) G20(-4.801,5.601) G21(-4.801,6.401) G22(-4.801,7.201) G24(-4.801,8.4) G25(-4.801,9.2) H1(-4,-9.601) H2(-4,-8.801) H3(-4,-8.001) H4(-4,-7.201) H5(-4,-6.401) H6(-4,-5.601) H7(-4,-4.801) H8(-4,-4) H9(-4,-2.751) H11(-4,-1.75) H12(-4,-0.749) H14(-4,0.749) H15(-4,1.75) H17(-4,2.751) H18(-4,4) H19(-4,4.801) H20(-4,5.601) H21(-4,6.401) H22(-4,7.201) H23(-4,8.001) H24(-4,8.801) H25(-4,9.601) J1(-3.2,-9.2) J2(-3.2,-8.4) J4(-3.2,-7.201) J5(-2.751,-6.401) J6(-2.751,-5.601) J7(-2.751,-4.801) J8(-2.751,-4) J9(-3.2,-3.2) J10(-3.2,-2.4) J11(-3.2,-1.6) J12(-3.2,-0.5) J14(-3.2,0.5) J15(-3.2,1.6) J16(-3.2,2.4) J17(-3.2,3.2) J18(-2.751,4) J19(-2.751,4.801) J20(-2.751,5.601) J21(-2.751,6.401) J22(-3.2,7.201) J24(-3.2,8.4) J25(-3.2,9.2) K1(-2.4,-9.601) K2(-2.4,-8.801) K3(-2.4,-8.001) K4(-2.4,-7.201) K9(-2.4,-3.2) K10(-2.4,-2.4) K11(-2.4,-1.6) K12(-2.4,-0.5) K14(-2.4,0.5) K15(-2.4,1.6) K16(-2.4,2.4) K17(-2.4,3.2) K22(-2.4,7.201) K23(-2.4,8.001) K24(-2.4,8.801) K25(-2.4,9.601) L1(-1.6,-9.2) L2(-1.6,-8.4) L4(-1.6,-7.201) L5(-1.75,-6.401) L6(-1.75,-5.601) L7(-1.75,-4.801) L8(-1.75,-4) L9(-1.6,-3.2) L10(-1.6,-2.4) L11(-1.6,-1.6) L12(-1.6,-0.5) L14(-1.6,0.5) L15(-1.6,1.6) L16(-1.6,2.4) L17(-1.6,3.2) L18(-1.75,4) L19(-1.75,4.801) L20(-1.75,5.601) L21(-1.75,6.401) L22(-1.6,7.201) L24(-1.6,8.4) L25(-1.6,9.2) M1(-0.8,-9.601) M2(-0.8,-8.801) M3(-0.8,-8.001) M4(-0.8,-7.201) M5(-0.749,-6.401) M6(-0.749,-5.601) M7(-0.749,-4.801) M8(-0.749,-4) M9(-0.5,-3.2) M10(-0.5,-2.4) M11(-0.5,-1.6) M12(-0.8,-0.8) M13(-0.8,0) M14(-0.8,0.8) M15(-0.5,1.6) M16(-0.5,2.4) M17(-0.5,3.2) M18(-0.749,4) M19(-0.749,4.801) M20(-0.749,5.601) M21(-0.749,6.401) M22(-0.8,7.201) M23(-0.8,8.001) M24(-0.8,8.801) M25(-0.8,9.601) N1(0,-9.2) N2(0,-8.4) N4(0,-7.201) N12(0,-0.8) N13(0,0) N14(0,0.8) N22(0,7.201) N24(0,8.4) N25(0,9.2) P1(0.8,-9.601) P2(0.8,-8.801) P3(0.8,-8.001) P4(0.8,-7.201) P5(0.749,-6.401) P6(0.749,-5.601) P7(0.749,-4.801) P8(0.749,-4) P9(0.5,-3.2) P10(0.5,-2.4) P11(0.5,-1.6) P12(0.8,-0.8) P13(0.8,0) P14(0.8,0.8) P15(0.5,1.6) P16(0.5,2.4) P17(0.5,3.2) P18(0.749,4) P19(0.749,4.801) P20(0.749,5.601) P21(0.749,6.401) P22(0.8,7.201) P23(0.8,8.001) P24(0.8,8.801) P25(0.8,9.601) R1(1.6,-9.2) R2(1.6,-8.4) R4(1.6,-7.201) R5(1.75,-6.401) R6(1.75,-5.601) R7(1.75,-4.801) R8(1.75,-4) R9(1.6,-3.2) R10(1.6,-2.4) R11(1.6,-1.6) R12(1.6,-0.5) R14(1.6,0.5) R15(1.6,1.6) R16(1.6,2.4) R17(1.6,3.2) R18(1.75,4) R19(1.75,4.801) R20(1.75,5.601) R21(1.75,6.401) R22(1.6,7.201) R24(1.6,8.4) R25(1.6,9.2) T1(2.4,-9.601) T2(2.4,-8.801) T3(2.4,-8.001) T4(2.4,-7.201) T9(2.4,-3.2) T10(2.4,-2.4) T11(2.4,-1.6) T12(2.4,-0.5) T14(2.4,0.5) T15(2.4,1.6) T16(2.4,2.4) T17(2.4,3.2) T22(2.4,7.201) T23(2.4,8.001) T24(2.4,8.801) T25(2.4,9.601) U1(3.2,-9.2) U2(3.2,-8.4) U4(3.2,-7.201) U5(2.751,-6.401) U6(2.751,-5.601) U7(2.751,-4.801) U8(2.751,-4) U9(3.2,-3.2) U10(3.2,-2.4) U11(3.2,-1.6) U12(3.2,-0.5) U14(3.2,0.5) U15(3.2,1.6) U16(3.2,2.4) U17(3.2,3.2) U18(2.751,4) U19(2.751,4.801) U20(2.751,5.601) U21(2.751,6.401) U22(3.2,7.201) U24(3.2,8.4) U25(3.2,9.2) V1(4,-9.601) V2(4,-8.801) V3(4,-8.001) V4(4,-7.201) V5(4,-6.401) V6(4,-5.601) V7(4,-4.801) V8(4,-4) V9(4,-2.751) V11(4,-1.75) V12(4,-0.749) V14(4,0.749) V15(4,1.75) V17(4,2.751) V18(4,4) V19(4,4.801) V20(4,5.601) V21(4,6.401) V22(4,7.201) V23(4,8.001) V24(4,8.801) V25(4,9.601) W1(4.801,-9.2) W2(4.801,-8.4) W4(4.801,-7.201) W5(4.801,-6.401) W6(4.801,-5.601) W7(4.801,-4.801) W8(4.801,-4) W9(4.801,-2.751) W11(4.801,-1.75) W12(4.801,-0.749) W14(4.801,0.749) W15(4.801,1.75) W17(4.801,2.751) W18(4.801,4) W19(4.801,4.801) W20(4.801,5.601) W21(4.801,6.401) W22(4.801,7.201) W24(4.801,8.4) W25(4.801,9.2) Y1(5.601,-9.601) Y2(5.601,-8.801) Y3(5.601,-8.001) Y4(5.601,-7.201) Y5(5.601,-6.401) Y6(5.601,-5.601) Y7(5.601,-4.801) Y8(5.601,-4) Y9(5.601,-2.751) Y11(5.601,-1.75) Y12(5.601,-0.749) Y14(5.601,0.749) Y15(5.601,1.75) Y17(5.601,2.751) Y18(5.601,4) Y19(5.601,4.801) Y20(5.601,5.601) Y21(5.601,6.401) Y22(5.601,7.201) Y23(5.601,8.001) Y24(5.601,8.801) Y25(5.601,9.601)
BGA605_080P230L230W207H
  round 0.406 smd: A2(-10.8,-10) A28(-10.8,10) AH1(10,-10.8) AH2(10,-10) AH28(10,10) AH29(10,10.8) AJ2(10.8,-10) AJ28(10.8,10) B1(-10,-10.8) B2(-10,-10) B28(-10,10) B29(-10,10.8) N13(-1.001,-1.001) N15(-1.001,0) N17(-1.001,1.001) R13(0,-1.001) R15(0,0) R17(0,1.001) U13(1.001,-1.001) U15(1.001,0) U17(1.001,1.001)
  round 0.305 smd: A3(-10.8,-9.2) A4(-10.8,-8.4) A5(-10.8,-7.6) A6(-10.399,-6.8) A7(-10.8,-5.999) A8(-10.399,-5.199) A9(-10.8,-4.399) A10(-10.399,-3.599) A11(-10.8,-2.799) A12(-10.399,-1.999) A13(-10.8,-1.199) A14(-10.399,-0.399) A16(-10.8,0.399) A17(-10.399,1.199) A18(-10.8,1.999) A19(-10.399,2.799) A20(-10.8,3.599) A21(-10.399,4.399) A22(-10.8,5.199) A23(-10.399,5.999) A24(-10.8,6.8) A25(-10.399,7.6) A26(-10.8,8.4) A27(-10.8,9.2) AA1(4.399,-10.8) AA2(4.399,-10) AA3(4.399,-9.2) AA4(4.399,-8.4) AA5(4.026,-7.501) AA6(4.026,-6.701) AA7(4.026,-5.9) AA8(4.026,-5.1) AA9(4.3,-4.3) AA10(4.3,-3.5) AA11(4.3,-2.7) AA12(4.3,-1.9) AA14(4.3,-0.599) AA16(4.3,0.599) AA18(4.3,1.9) AA19(4.3,2.7) AA20(4.3,3.5) AA21(4.3,4.3) AA22(4.026,5.1) AA23(4.026,5.9) AA24(4.026,6.701) AA25(4.026,7.501) AA26(4.399,8.4) AA28(4.399,9.601) AA29(4.399,10.399) AB1(5.199,-10.399) AB2(5.199,-9.601) AB4(5.199,-8.4) AB5(5.1,-7.501) AB6(5.1,-6.701) AB7(5.1,-5.9) AB9(5.1,-4.026) AB11(5.1,-2.875) AB12(5.1,-1.725) AB14(5.1,-0.574) AB16(5.1,0.574) AB18(5.1,1.725) AB19(5.1,2.875) AB21(5.1,4.026) AB23(5.1,5.9) AB24(5.1,6.701) AB25(5.1,7.501) AB26(5.199,8.4) AB27(5.199,9.2) AB28(5.199,10) AB29(5.199,10.8) AC1(5.999,-10.8) AC2(5.999,-10) AC3(5.999,-9.2) AC4(5.999,-8.4) AC5(5.9,-7.501) AC6(5.9,-6.701) AC8(5.9,-5.1) AC9(5.9,-4.026) AC11(5.9,-2.875) AC12(5.9,-1.725) AC14(5.9,-0.574) AC16(5.9,0.574) AC18(5.9,1.725) AC19(5.9,2.875) AC21(5.9,4.026) AC22(5.9,5.1) AC24(5.9,6.701) AC25(5.9,7.501) AC26(5.999,8.4) AC28(5.999,9.601) AC29(5.999,10.399) AD1(6.8,-10.399) AD2(6.8,-9.601) AD4(6.8,-8.4) AD5(6.701,-7.501) AD6(6.701,-6.701) AD7(6.701,-5.9) AD8(6.701,-5.1) AD9(6.701,-4.026) AD11(6.701,-2.875) AD12(6.701,-1.725) AD14(6.701,-0.574) AD16(6.701,0.574) AD18(6.701,1.725) AD19(6.701,2.875) AD21(6.701,4.026) AD22(6.701,5.1) AD23(6.701,5.9) AD24(6.701,6.701) AD25(6.701,7.501) AD26(6.8,8.4) AD27(6.8,9.2) AD28(6.8,10) AD29(6.8,10.8) AE1(7.6,-10.8) AE2(7.6,-10) AE3(7.6,-9.2) AE4(7.6,-8.4) AE5(7.501,-7.501) AE6(7.501,-6.701) AE7(7.501,-5.9) AE8(7.501,-5.1) AE9(7.501,-4.026) AE11(7.501,-2.875) AE12(7.501,-1.725) AE14(7.501,-0.574) AE16(7.501,0.574) AE18(7.501,1.725) AE19(7.501,2.875) AE21(7.501,4.026) AE22(7.501,5.1) AE23(7.501,5.9) AE24(7.501,6.701) AE25(7.501,7.501) AE26(7.6,8.4) AE28(7.6,9.601) AE29(7.6,10.399) AF1(8.4,-10.8) AF2(8.4,-10) AF3(8.4,-9.2) AF4(8.4,-8.4) AF5(8.4,-7.6) AF6(8.4,-6.8) AF7(8.4,-5.999) AF8(8.4,-5.199) AF9(8.4,-4.399) AF10(8.4,-3.599) AF11(8.4,-2.799) AF12(8.4,-1.999) AF13(8.4,-1.199) AF14(8.4,-0.399) AF16(8.4,0.399) AF17(8.4,1.199) AF18(8.4,1.999) AF19(8.4,2.799) AF20(8.4,3.599) AF21(8.4,4.399) AF22(8.4,5.199) AF23(8.4,5.999) AF24(8.4,6.8) AF25(8.4,7.6) AF26(8.4,8.4) AF27(8.4,9.2) AF28(8.4,10) AF29(8.4,10.8) AG1(9.2,-10.8) AG2(9.2,-10) AG4(9.2,-8.4) AG6(9.2,-6.8) AG8(9.2,-5.199) AG10(9.2,-3.599) AG12(9.2,-1.999) AG14(9.2,-0.399) AG17(9.2,1.199) AG19(9.2,2.799) AG21(9.2,4.399) AG23(9.2,5.999) AG25(9.2,7.6) AG26(9.2,8.4) AG28(9.2,10) AG29(9.2,10.8) AH3(10,-9.2) AH4(10,-8.4) AH5(9.601,-7.6) AH6(10,-6.8) AH7(9.601,-5.999) AH8(10,-5.199) AH9(9.601,-4.399) AH10(10,-3.599) AH11(9.601,-2.799) AH12(10,-1.999) AH13(9.601,-1.199) AH14(10,-0.399) AH16(9.601,0.399) AH17(10,1.199) AH18(9.601,1.999) AH19(10,2.799) AH20(9.601,3.599) AH21(10,4.399) AH22(9.601,5.199) AH23(10,5.999) AH24(9.601,6.8) AH25(10,7.6) AH26(10,8.4) AH27(10,9.2) AJ3(10.8,-9.2) AJ4(10.8,-8.4) AJ5(10.399,-7.6) AJ6(10.8,-6.8) AJ7(10.399,-5.999) AJ8(10.8,-5.199) AJ9(10.399,-4.399) AJ10(10.8,-3.599) AJ11(10.399,-2.799) AJ12(10.8,-1.999) AJ13(10.399,-1.199) AJ14(10.8,-0.399) AJ16(10.399,0.399) AJ17(10.8,1.199) AJ18(10.399,1.999) AJ19(10.8,2.799) AJ20(10.399,3.599) AJ21(10.8,4.399) AJ22(10.399,5.199) AJ23(10.8,5.999) AJ24(10.399,6.8) AJ25(10.8,7.6) AJ26(10.8,8.4) AJ27(10.8,9.2) B3(-10,-9.2) B4(-10,-8.4) B5(-10,-7.6) B6(-9.601,-6.8) B7(-10,-5.999) B8(-9.601,-5.199) B9(-10,-4.399) B10(-9.601,-3.599) B11(-10,-2.799) B12(-9.601,-1.999) B13(-10,-1.199) B14(-9.601,-0.399) B16(-10,0.399) B17(-9.601,1.199) B18(-10,1.999) B19(-9.601,2.799) B20(-10,3.599) B21(-9.601,4.399) B22(-10,5.199) B23(-9.601,5.999) B24(-10,6.8) B25(-9.601,7.6) B26(-10,8.4) B27(-10,9.2) C1(-9.2,-10.8) C2(-9.2,-10) C4(-9.2,-8.4) C5(-9.2,-7.6) C7(-9.2,-5.999) C9(-9.2,-4.399) C11(-9.2,-2.799) C13(-9.2,-1.199) C16(-9.2,0.399) C18(-9.2,1.999) C20(-9.2,3.599) C22(-9.2,5.199) C24(-9.2,6.8) C26(-9.2,8.4) C28(-9.2,10) C29(-9.2,10.8) D1(-8.4,-10.8) D2(-8.4,-10) D3(-8.4,-9.2) D4(-8.4,-8.4) D5(-8.4,-7.6) D6(-8.4,-6.8) D7(-8.4,-5.999) D8(-8.4,-5.199) D9(-8.4,-4.399) D10(-8.4,-3.599) D11(-8.4,-2.799) D12(-8.4,-1.999) D13(-8.4,-1.199) D14(-8.4,-0.399) D16(-8.4,0.399) D17(-8.4,1.199) D18(-8.4,1.999) D19(-8.4,2.799) D20(-8.4,3.599) D21(-8.4,4.399) D22(-8.4,5.199) D23(-8.4,5.999) D24(-8.4,6.8) D25(-8.4,7.6) D26(-8.4,8.4) D27(-8.4,9.2) D28(-8.4,10) D29(-8.4,10.8) E1(-7.6,-10.399) E2(-7.6,-9.601) E4(-7.6,-8.4) E5(-7.501,-7.501) E6(-7.501,-6.701) E7(-7.501,-5.9) E8(-7.501,-5.1) E9(-7.501,-4.026) E11(-7.501,-2.875) E12(-7.501,-1.725) E14(-7.501,-0.574) E16(-7.501,0.574) E18(-7.501,1.725) E19(-7.501,2.875) E21(-7.501,4.026) E22(-7.501,5.1) E23(-7.501,5.9) E24(-7.501,6.701) E25(-7.501,7.501) E26(-7.6,8.4) E27(-7.6,9.2) E28(-7.6,10) E29(-7.6,10.8) F1(-6.8,-10.8) F2(-6.8,-10) F3(-6.8,-9.2) F4(-6.8,-8.4) F5(-6.701,-7.501) F6(-6.701,-6.701) F7(-6.701,-5.9) F8(-6.701,-5.1) F9(-6.701,-4.026) F11(-6.701,-2.875) F12(-6.701,-1.725) F14(-6.701,-0.574) F16(-6.701,0.574) F18(-6.701,1.725) F19(-6.701,2.875) F21(-6.701,4.026) F22(-6.701,5.1) F23(-6.701,5.9) F24(-6.701,6.701) F25(-6.701,7.501) F26(-6.8,8.4) F28(-6.8,9.601) F29(-6.8,10.399) G1(-5.999,-10.399) G2(-5.999,-9.601) G4(-5.999,-8.4) G5(-5.9,-7.501) G6(-5.9,-6.701) G8(-5.9,-5.1) G9(-5.9,-4.026) G11(-5.9,-2.875) G12(-5.9,-1.725) G14(-5.9,-0.574) G16(-5.9,0.574) G18(-5.9,1.725) G19(-5.9,2.875) G21(-5.9,4.026) G22(-5.9,5.1) G24(-5.9,6.701) G25(-5.9,7.501) G26(-5.999,8.4) G27(-5.999,9.2) G28(-5.999,10) G29(-5.999,10.8) H1(-5.199,-10.8) H2(-5.199,-10) H3(-5.199,-9.2) H4(-5.199,-8.4) H5(-5.1,-7.501) H6(-5.1,-6.701) H7(-5.1,-5.9) H9(-5.1,-4.026) H11(-5.1,-2.875) H12(-5.1,-1.725) H14(-5.1,-0.574) H16(-5.1,0.574) H18(-5.1,1.725) H19(-5.1,2.875) H21(-5.1,4.026) H23(-5.1,5.9) H24(-5.1,6.701) H25(-5.1,7.501) H26(-5.199,8.4) H28(-5.199,9.601) H29(-5.199,10.399) J1(-4.399,-10.399) J2(-4.399,-9.601) J4(-4.399,-8.4) J5(-4.026,-7.501) J6(-4.026,-6.701) J7(-4.026,-5.9) J8(-4.026,-5.1) J9(-4.3,-4.3) J10(-4.3,-3.5) J11(-4.3,-2.7) J12(-4.3,-1.9) J14(-4.3,-0.599) J16(-4.3,0.599) J18(-4.3,1.9) J19(-4.3,2.7) J20(-4.3,3.5) J21(-4.3,4.3) J22(-4.026,5.1) J23(-4.026,5.9) J24(-4.026,6.701) J25(-4.026,7.501) J26(-4.399,8.4) J27(-4.399,9.2) J28(-4.399,10) J29(-4.399,10.8) K1(-3.599,-10.8) K2(-3.599,-10) K3(-3.599,-9.2) K4(-3.599,-8.4) K9(-3.5,-4.3) K10(-3.5,-3.5) K11(-3.5,-2.7) K12(-3.5,-1.9) K14(-3.5,-0.599) K16(-3.5,0.599) K18(-3.5,1.9) K19(-3.5,2.7) K20(-3.5,3.5) K21(-3.5,4.3) K26(-3.599,8.4) K28(-3.599,9.601) K29(-3.599,10.399) L1(-2.799,-10.399) L2(-2.799,-9.601) L4(-2.799,-8.4) L5(-2.875,-7.501) L6(-2.875,-6.701) L7(-2.875,-5.9) L8(-2.875,-5.1) L9(-2.7,-4.3) L10(-2.7,-3.5) L12(-2.7,-1.9) L18(-2.7,1.9) L20(-2.7,3.5) L21(-2.7,4.3) L22(-2.875,5.1) L23(-2.875,5.9) L24(-2.875,6.701) L25(-2.875,7.501) L26(-2.799,8.4) L27(-2.799,9.2) L28(-2.799,10) L29(-2.799,10.8) M1(-1.999,-10.8) M2(-1.999,-10) M3(-1.999,-9.2) M4(-1.999,-8.4) M5(-1.725,-7.501) M6(-1.725,-6.701) M7(-1.725,-5.9) M8(-1.725,-5.1) M9(-1.9,-4.3) M10(-1.9,-3.5) M11(-1.9,-2.7) M12(-1.9,-1.9) M18(-1.9,1.9) M19(-1.9,2.7) M20(-1.9,3.5) M21(-1.9,4.3) M22(-1.725,5.1) M23(-1.725,5.9) M24(-1.725,6.701) M25(-1.725,7.501) M26(-1.999,8.4) M28(-1.999,9.601) M29(-1.999,10.399) N1(-1.199,-10.399) N2(-1.199,-9.601) N4(-1.199,-8.4) N26(-1.199,8.4) N27(-1.199,9.2) N28(-1.199,10) N29(-1.199,10.8) P1(-0.399,-10.8) P2(-0.399,-10) P3(-0.399,-9.2) P4(-0.399,-8.4) P5(-0.574,-7.501) P6(-0.574,-6.701) P7(-0.574,-5.9) P8(-0.574,-5.1) P9(-0.599,-4.3) P10(-0.599,-3.5) P20(-0.599,3.5) P21(-0.599,4.3) P22(-0.574,5.1) P23(-0.574,5.9) P24(-0.574,6.701) P25(-0.574,7.501) P26(-0.399,8.4) P28(-0.399,9.601) P29(-0.399,10.399) T1(0.399,-10.399) T2(0.399,-9.601) T4(0.399,-8.4) T5(0.574,-7.501) T6(0.574,-6.701) T7(0.574,-5.9) T8(0.574,-5.1) T9(0.599,-4.3) T10(0.599,-3.5) T20(0.599,3.5) T21(0.599,4.3) T22(0.574,5.1) T23(0.574,5.9) T24(0.574,6.701) T25(0.574,7.501) T26(0.399,8.4) T27(0.399,9.2) T28(0.399,10) T29(0.399,10.8) U1(1.199,-10.8) U2(1.199,-10) U3(1.199,-9.2) U4(1.199,-8.4) U26(1.199,8.4) U28(1.199,9.601) U29(1.199,10.399) V1(1.999,-10.399) V2(1.999,-9.601) V4(1.999,-8.4) V5(1.725,-7.501) V6(1.725,-6.701) V7(1.725,-5.9) V8(1.725,-5.1) V9(1.9,-4.3) V10(1.9,-3.5) V11(1.9,-2.7) V12(1.9,-1.9) V18(1.9,1.9) V19(1.9,2.7) V20(1.9,3.5) V21(1.9,4.3) V22(1.725,5.1) V23(1.725,5.9) V24(1.725,6.701) V25(1.725,7.501) V26(1.999,8.4) V27(1.999,9.2) V28(1.999,10) V29(1.999,10.8) W1(2.799,-10.8) W2(2.799,-10) W3(2.799,-9.2) W4(2.799,-8.4) W5(2.875,-7.501) W6(2.875,-6.701) W7(2.875,-5.9) W8(2.875,-5.1) W9(2.7,-4.3) W10(2.7,-3.5) W12(2.7,-1.9) W18(2.7,1.9) W20(2.7,3.5) W21(2.7,4.3) W22(2.875,5.1) W23(2.875,5.9) W24(2.875,6.701) W25(2.875,7.501) W26(2.799,8.4) W28(2.799,9.601) W29(2.799,10.399) Y1(3.599,-10.399) Y2(3.599,-9.601) Y4(3.599,-8.4) Y9(3.5,-4.3) Y10(3.5,-3.5) Y11(3.5,-2.7) Y12(3.5,-1.9) Y14(3.5,-0.599) Y16(3.5,0.599) Y18(3.5,1.9) Y19(3.5,2.7) Y20(3.5,3.5) Y21(3.5,4.3) Y26(3.599,8.4) Y27(3.599,9.2) Y28(3.599,10) Y29(3.599,10.8)
